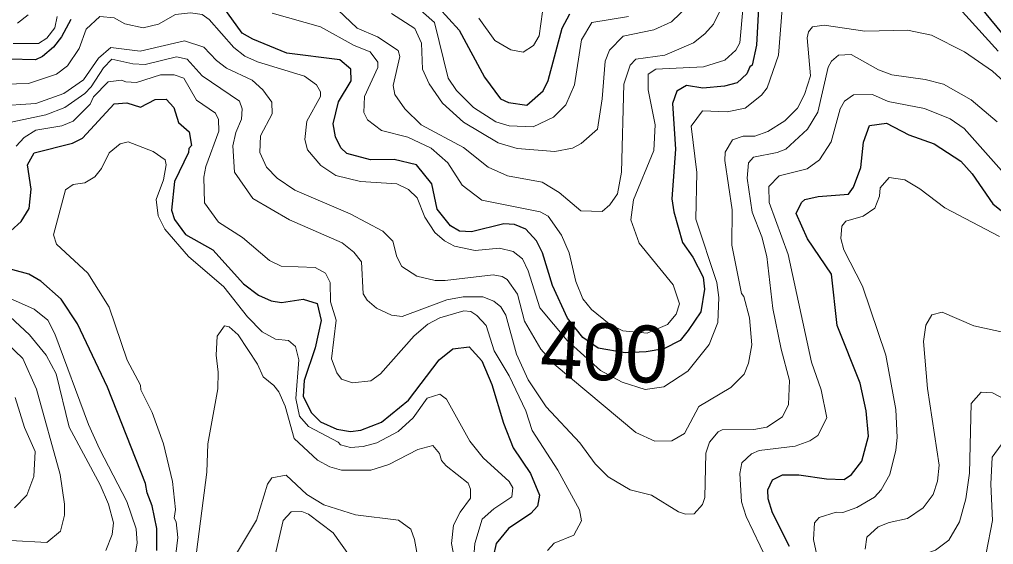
# Model space of a CAD drawing. Extents: x 673.3 to 698.5, y 6984.3 to 7012.3.
# Drawn here: x 682.878 to 684.245, y 6990.82 to 6991.558 of the extents above; entities that cross this region are included whole.
import ezdxf
from ezdxf.enums import TextEntityAlignment as Align

# ---------------------------------------------------------------- set-up
doc = ezdxf.new("R2010")
doc.units = 0
doc.header["$LTSCALE"] = 0.032
doc.layers.add('1', color=7, linetype='Continuous', lineweight=25)
doc.layers.add('2', color=7, linetype='Continuous', lineweight=13)
doc.layers.add('61', color=7, linetype='Continuous')

msp = doc.modelspace()

# ---------------------------------------------------------------- linework, layer by layer
at = {"layer": '1'}
for points in [[(683.917, 6991.6004), (683.9127, 6991.5214), (683.9064, 6991.4935), (683.903, 6991.4911), (683.8991, 6991.4815), (683.8853, 6991.4686), (683.8676, 6991.464), (683.8371, 6991.4611), (683.8145, 6991.4649), (683.8006, 6991.4571), (683.7946, 6991.4397), (683.7988, 6991.3753), (683.7939, 6991.3056), (683.7964, 6991.2876), (683.8086, 6991.2446), (683.8233, 6991.2238), (683.8379, 6991.1957), (683.8394, 6991.179), (683.8346, 6991.1472), (683.8167, 6991.1209), (683.8054, 6991.1069), (683.7824, 6991.0952), (683.7576, 6991.0908), (683.7284, 6991.0894), (683.6901, 6991.096), (683.6689, 6991.1108), (683.647, 6991.1381), (683.6263, 6991.1838), (683.6121, 6991.2301), (683.6037, 6991.2467), (683.5886, 6991.2632), (683.5726, 6991.2696), (683.5576, 6991.2705), (683.5126, 6991.2595), (683.4954, 6991.2603), (683.4829, 6991.268), (683.4641, 6991.291), (683.4565, 6991.327), (683.4354, 6991.3536), (683.4036, 6991.3609), (683.3704, 6991.3606), (683.3372, 6991.3696), (683.3289, 6991.3773), (683.3213, 6991.393), (683.3183, 6991.4109), (683.3258, 6991.4419), (683.3434, 6991.4713), (683.343, 6991.4877), (683.3277, 6991.501), (683.2529, 6991.5101), (683.2052, 6991.5299), (683.1906, 6991.5383), (683.1455, 6991.6011)], [(684.257, 6991.5387), (684.1974, 6991.6113)], [(683.4662, 6991.5746), (683.4951, 6991.5424), (683.5307, 6991.4764), (683.5531, 6991.4462), (683.5644, 6991.441), (683.5901, 6991.4374), (683.6131, 6991.4574), (683.6202, 6991.4719), (683.6399, 6991.5455), (683.6507, 6991.5655)], [(682.9497, 6991.5577), (682.9365, 6991.5331), (682.9255, 6991.5187), (682.91, 6991.5058), (682.9004, 6991.5011), (682.8631, 6991.5019)], [(682.8803, 6991.2741), (682.8913, 6991.292), (682.8939, 6991.3194), (682.8891, 6991.3534), (682.8985, 6991.3702), (682.9521, 6991.3841), (682.9662, 6991.391), (683.0108, 6991.4391), (683.0286, 6991.4407), (683.0476, 6991.4343), (683.0684, 6991.4453), (683.0837, 6991.4455), (683.0943, 6991.4339), (683.1011, 6991.4128), (683.1161, 6991.4), (683.1194, 6991.3806), (683.1156, 6991.3764), (683.1151, 6991.371), (683.0954, 6991.3299), (683.0911, 6991.2896), (683.0953, 6991.2768), (683.1109, 6991.2558), (683.1492, 6991.2342), (683.1923, 6991.1865), (683.2134, 6991.1703), (683.2312, 6991.1625), (683.2454, 6991.16), (683.2762, 6991.1646), (683.2955, 6991.1587), (683.3011, 6991.1346), (683.2931, 6991.0966), (683.2775, 6991.0504), (683.2759, 6991.0285), (683.2872, 6991.0054), (683.3006, 6990.9927), (683.3235, 6990.9822), (683.3424, 6990.9791), (683.357, 6990.9806), (683.3861, 6990.9922), (683.424, 6991.0228), (683.4672, 6991.0798), (683.4864, 6991.0951), (683.5093, 6991.0979), (683.5267, 6991.0783), (683.5411, 6991.0448), (683.5573, 6990.9905), (683.5709, 6990.956), (683.5953, 6990.9201), (683.608, 6990.8897), (683.6049, 6990.8739), (683.5956, 6990.8639), (683.5643, 6990.8425), (683.547, 6990.8216), (683.543, 6990.8028)], [(683.9589, 6990.8174), (683.9349, 6990.8647), (683.9291, 6990.8845), (683.9285, 6990.8972), (683.935, 6990.9112), (683.9489, 6990.9179), (683.9722, 6990.9179), (684.0107, 6990.9122), (684.0358, 6990.9116), (684.0459, 6990.9185), (684.0607, 6990.9371), (684.0699, 6990.9725), (684.0667, 6991.008), (684.0583, 6991.0466), (684.0259, 6991.128), (684.0178, 6991.2), (683.9843, 6991.2497), (683.9683, 6991.2852), (683.9756, 6991.3008), (683.9804, 6991.3047), (683.999, 6991.3088), (684.0416, 6991.3124), (684.0487, 6991.3219), (684.0593, 6991.3499), (684.0628, 6991.3854), (684.0714, 6991.4086), (684.0949, 6991.4119), (684.1264, 6991.3958)], [(684.1264, 6991.3958), (684.1622, 6991.3828), (684.1994, 6991.3585), (684.2154, 6991.3408), (684.2445, 6991.2988), (684.2832, 6991.2673)], [(682.836, 6991.2346), (682.8803, 6991.2741)], [(683.0706, 6990.8117), (683.0706, 6990.8425), (683.0642, 6990.8745), (683.0568, 6990.8929), (683.0546, 6990.9061), (683.0013, 6991.0412), (682.9593, 6991.1302), (682.9362, 6991.1649), (682.9076, 6991.1901), (682.8909, 6991.1997), (682.8405, 6991.2135)]]:
    msp.add_lwpolyline(points, dxfattribs=at)
at = {"layer": '2'}
for points in [[(683.2982, 6991.5968), (683.3519, 6991.5455), (683.3804, 6991.5334), (683.4092, 6991.5141), (683.4117, 6991.5056), (683.4022, 6991.4647), (683.4046, 6991.4521), (683.419, 6991.4321), (683.4415, 6991.4095), (683.5014, 6991.3778), (683.5359, 6991.3502), (683.5631, 6991.338), (683.6117, 6991.329), (683.6356, 6991.3147), (683.6658, 6991.289), (683.6959, 6991.2878), (683.7066, 6991.2973), (683.7173, 6991.3126), (683.7229, 6991.3432), (683.7263, 6991.4666), (683.7352, 6991.4935), (683.7432, 6991.502), (683.7837, 6991.5075), (683.8239, 6991.525), (683.8399, 6991.5373), (683.852, 6991.551), (683.865, 6991.5769)], [(683.8173, 6991.5773), (683.7933, 6991.5542), (683.7682, 6991.543), (683.7252, 6991.5342), (683.7063, 6991.5146), (683.7002, 6991.4993), (683.6961, 6991.4462), (683.6895, 6991.4035), (683.6665, 6991.3836), (683.6542, 6991.3769), (683.6293, 6991.3723), (683.5765, 6991.3765), (683.5499, 6991.3843), (683.5012, 6991.4134), (683.4719, 6991.4402), (683.4529, 6991.4671), (683.4437, 6991.4879), (683.442, 6991.5246), (683.4328, 6991.5451), (683.3999, 6991.566)], [(683.426, 6991.5839), (683.4605, 6991.5533), (683.4797, 6991.4752), (683.4912, 6991.4577), (683.5151, 6991.4338), (683.5465, 6991.4137), (683.5652, 6991.4082), (683.5991, 6991.4067), (683.6277, 6991.4202), (683.6448, 6991.4376), (683.6572, 6991.466), (683.6667, 6991.5292), (683.6813, 6991.5535), (683.7329, 6991.562)], [(683.894, 6991.5768), (683.8891, 6991.5247), (683.8835, 6991.5145), (683.8681, 6991.5006), (683.8383, 6991.4913), (683.7713, 6991.488), (683.7603, 6991.4806), (683.7603, 6991.459), (683.7702, 6991.4096), (683.7686, 6991.3738), (683.7398, 6991.3042), (683.7361, 6991.276), (683.7477, 6991.2433), (683.7958, 6991.1848), (683.8045, 6991.1584), (683.7996, 6991.1438), (683.7876, 6991.1293), (683.759, 6991.1171), (683.725, 6991.1202), (683.7058, 6991.1303), (683.6811, 6991.1505), (683.6689, 6991.1653)], [(684.1929, 6991.5783), (684.2517, 6991.513)], [(682.8567, 6991.4669), (682.8902, 6991.4677), (682.9297, 6991.481), (682.945, 6991.4926), (682.9614, 6991.5171), (682.9714, 6991.5442), (682.9906, 6991.5619), (683.0105, 6991.5598), (683.0257, 6991.5513), (683.0512, 6991.5458), (683.073, 6991.5511), (683.0968, 6991.5645), (683.1179, 6991.5671), (683.1342, 6991.5645), (683.1441, 6991.5578)], [(682.9305, 6991.5618), (682.9273, 6991.5461), (682.9159, 6991.5312), (682.9045, 6991.5239), (682.8688, 6991.5239)], [(682.8751, 6991.5525), (682.8899, 6991.5644)], [(683.1441, 6991.5578), (683.1788, 6991.5184), (683.1942, 6991.5062), (683.2117, 6991.4982), (683.2778, 6991.4781), (683.2946, 6991.466), (683.3002, 6991.4562), (683.3003, 6991.4493), (683.2811, 6991.4149), (683.2784, 6991.3891), (683.282, 6991.3747), (683.3009, 6991.3524), (683.3217, 6991.3385), (683.3567, 6991.3301), (683.4075, 6991.3267), (683.4241, 6991.3186), (683.4362, 6991.3072), (683.447, 6991.2799), (683.4611, 6991.2586), (683.4746, 6991.2465), (683.4884, 6991.2391), (683.5176, 6991.2331), (683.5517, 6991.2363), (683.5711, 6991.2317), (683.5838, 6991.2214), (683.5922, 6991.2047), (683.6084, 6991.1525), (683.6467, 6991.1065), (683.6934, 6991.0646), (683.7241, 6991.048), (683.7564, 6991.0377), (683.7827, 6991.0415), (683.8164, 6991.0635), (683.8459, 6991.1013), (683.8581, 6991.1322), (683.8597, 6991.167), (683.8567, 6991.1884), (683.8273, 6991.2771), (683.8288, 6991.3426), (683.8209, 6991.4079), (683.8369, 6991.4291), (683.8716, 6991.4278), (683.8968, 6991.433), (683.9197, 6991.4511), (683.9274, 6991.4614), (683.9437, 6991.5074), (683.9484, 6991.5728)], [(683.6689, 6991.1653), (683.6591, 6991.1895), (683.6495, 6991.2301), (683.6389, 6991.2546), (683.6199, 6991.2816), (683.6086, 6991.2876), (683.527, 6991.3038), (683.4995, 6991.3247), (683.4792, 6991.3563), (683.4556, 6991.3771), (683.4231, 6991.3925), (683.386, 6991.4019), (683.3665, 6991.4168), (683.3614, 6991.4269), (683.3621, 6991.4495), (683.381, 6991.49), (683.3808, 6991.4979), (683.3702, 6991.5123), (683.3478, 6991.5212), (683.3006, 6991.5473), (683.2327, 6991.5666)], [(683.6123, 6991.5686), (683.6073, 6991.5345), (683.5995, 6991.5209), (683.585, 6991.5117), (683.5677, 6991.5152), (683.545, 6991.5283), (683.5225, 6991.5596)], [(683.9014, 6991.0748), (683.9062, 6991.1006), (683.9029, 6991.1386), (683.8949, 6991.1685), (683.8916, 6991.1729), (683.8778, 6991.2406), (683.8785, 6991.2904), (683.868, 6991.3595), (683.8684, 6991.3711), (683.8789, 6991.3886), (683.8938, 6991.3936), (683.9101, 6991.3937), (683.9285, 6991.4005), (683.9526, 6991.4152), (683.9703, 6991.4332), (683.9799, 6991.4522), (683.9883, 6991.4784), (683.9836, 6991.5317), (683.9856, 6991.5401), (683.9912, 6991.5475), (684.0075, 6991.5498), (684.0649, 6991.541), (684.1248, 6991.5425), (684.1582, 6991.5354), (684.2046, 6991.5123), (684.2438, 6991.4851), (684.2702, 6991.4612)], [(682.8446, 6991.436), (682.9008, 6991.4396), (682.9401, 6991.4536), (682.9676, 6991.473), (682.9888, 6991.5031), (683.0059, 6991.5181), (683.0472, 6991.5133), (683.1095, 6991.5277), (683.1365, 6991.5188), (683.1543, 6991.5), (683.1686, 6991.4892), (683.2042, 6991.4725), (683.2192, 6991.459), (683.232, 6991.4417), (683.2326, 6991.4251), (683.216, 6991.3944), (683.2152, 6991.3709), (683.2247, 6991.3502), (683.2395, 6991.3346), (683.2645, 6991.3177), (683.3422, 6991.2846), (683.3881, 6991.2601), (683.4019, 6991.2463), (683.4075, 6991.2241), (683.4147, 6991.2107), (683.4355, 6991.1971), (683.4616, 6991.1912), (683.4752, 6991.1908), (683.5426, 6991.1989), (683.5554, 6991.1966), (683.5623, 6991.1924), (683.5772, 6991.172), (683.5869, 6991.134), (683.6099, 6991.0944), (683.6287, 6991.0734), (683.7431, 6990.9775), (683.7697, 6990.9651), (683.7935, 6990.9659), (683.8114, 6990.9763), (683.8315, 6991.0142), (683.8767, 6991.0407), (683.8954, 6991.0594), (683.9014, 6991.0748)], [(682.866, 6991.4132), (682.9146, 6991.4237), (682.9416, 6991.4342), (682.9693, 6991.4535), (682.9784, 6991.4632), (682.9956, 6991.4898), (683.0075, 6991.5017), (683.0367, 6991.4953), (683.0541, 6991.4946), (683.0983, 6991.5051), (683.1133, 6991.502), (683.1341, 6991.4784), (683.1866, 6991.4427), (683.1903, 6991.4323), (683.1896, 6991.4177), (683.1814, 6991.3989), (683.1774, 6991.38), (683.1796, 6991.3432), (683.2052, 6991.3064), (683.2569, 6991.276), (683.3308, 6991.2439), (683.3471, 6991.231), (683.3581, 6991.2174), (683.3605, 6991.1723), (683.3658, 6991.1634), (683.3791, 6991.1521), (683.4003, 6991.1422), (683.4151, 6991.1403), (683.4779, 6991.1638), (683.5009, 6991.168), (683.5283, 6991.1679), (683.5436, 6991.1622), (683.5536, 6991.1541), (683.5608, 6991.1422), (683.5757, 6991.0875), (683.592, 6991.0513), (683.6174, 6991.0135), (683.6647, 6990.9632), (683.686, 6990.9337), (683.7042, 6990.9154), (683.7352, 6990.8972), (683.7653, 6990.8894), (683.8031, 6990.8661), (683.8128, 6990.8627), (683.8252, 6990.8632), (683.8369, 6990.8763), (683.8402, 6990.8863), (683.8416, 6990.9487), (683.8467, 6990.9641), (683.8587, 6990.9786), (683.8642, 6990.9814), (683.9088, 6990.9815), (683.9271, 6990.9852), (683.9489, 6990.9997), (683.9575, 6991.0166), (683.9591, 6991.0507), (683.947, 6991.0944), (683.9355, 6991.1519)], [(683.9355, 6991.1519), (683.9273, 6991.2249), (683.9201, 6991.2524), (683.9063, 6991.2871), (683.8997, 6991.3347), (683.9014, 6991.3565), (683.9082, 6991.3642), (683.9417, 6991.3707), (683.9539, 6991.3756), (683.9841, 6991.4036), (683.9985, 6991.4275), (684.013, 6991.4907), (684.018, 6991.4989), (684.0275, 6991.5074), (684.0454, 6991.5083), (684.084, 6991.487), (684.1027, 6991.48), (684.1495, 6991.4732), (684.1753, 6991.4667), (684.2138, 6991.445), (684.2506, 6991.4138)], [(682.8729, 6991.3798), (682.8845, 6991.3919), (682.9007, 6991.4021), (682.9374, 6991.4082), (682.9531, 6991.4146), (682.9768, 6991.4389), (682.9818, 6991.449), (683.002, 6991.4701), (683.021, 6991.4726), (683.027, 6991.47), (683.0421, 6991.4693), (683.0755, 6991.4798), (683.0951, 6991.4798), (683.1085, 6991.4751), (683.1263, 6991.4445), (683.1529, 6991.4259), (683.157, 6991.4173), (683.1577, 6991.4008), (683.1396, 6991.3511), (683.1367, 6991.3363), (683.1375, 6991.3), (683.1571, 6991.2728), (683.191, 6991.2512), (683.2289, 6991.2191), (683.2452, 6991.2112), (683.2928, 6991.2093), (683.3075, 6991.2015), (683.3141, 6991.188), (683.3142, 6991.1612), (683.3223, 6991.1354), (683.3158, 6991.0809), (683.3235, 6991.0613), (683.3298, 6991.0524), (683.3453, 6991.0475), (683.371, 6991.0499), (683.3845, 6991.06), (683.432, 6991.1132), (683.4512, 6991.1298), (683.4681, 6991.1386), (683.5017, 6991.1482), (683.5114, 6991.1476), (683.52, 6991.142), (683.5331, 6991.1279), (683.5444, 6991.092), (683.5651, 6991.057), (683.5889, 6991.0078), (683.5977, 6990.9804), (683.6337, 6990.9248), (683.6639, 6990.8689), (683.6667, 6990.8536), (683.656, 6990.8335), (683.6287, 6990.8219), (683.6192, 6990.8117)], [(683.9275, 6990.7976), (683.8983, 6990.8596), (683.8915, 6990.8799), (683.8891, 6990.92), (683.8922, 6990.9351), (683.9054, 6990.9474), (683.9161, 6990.9521), (683.9671, 6990.9584), (683.9874, 6990.9658), (683.9987, 6990.9731), (684.0113, 6990.9982), (684.0032, 6991.0374), (683.9897, 6991.0765), (683.9569, 6991.2276), (683.9305, 6991.3005), (683.9299, 6991.3232), (683.9446, 6991.3382), (683.9838, 6991.3477), (684.0009, 6991.3605), (684.0175, 6991.3857), (684.0301, 6991.4321), (684.0361, 6991.4427), (684.0487, 6991.452), (684.0756, 6991.4521)], [(684.0756, 6991.4521), (684.0974, 6991.4426), (684.1484, 6991.4328), (684.1845, 6991.4181), (684.2041, 6991.4043), (684.2751, 6991.3244)], [(683.5162, 6990.8094), (683.5173, 6990.8214), (683.5275, 6990.8558), (683.5436, 6990.8704), (683.5691, 6990.8871), (683.5706, 6990.9), (683.5655, 6990.9086), (683.5288, 6990.942), (683.51, 6990.9655), (683.4772, 6991.0244), (683.468, 6991.0312), (683.45, 6991.0258), (683.4307, 6990.9979), (683.4094, 6990.9787), (683.3796, 6990.9629), (683.3604, 6990.9578), (683.3427, 6990.9563), (683.3283, 6990.9603), (683.3251, 6990.9641), (683.2836, 6990.9859), (683.2711, 6991.0005), (683.2657, 6991.0253), (683.2698, 6991.0797), (683.2652, 6991.0985), (683.2553, 6991.1068), (683.2374, 6991.1088), (683.2184, 6991.1187), (683.1981, 6991.1398), (683.1647, 6991.1822), (683.115, 6991.2245), (683.0816, 6991.2631), (683.0726, 6991.282), (683.0698, 6991.3047), (683.0797, 6991.3322), (683.0837, 6991.3534), (683.0821, 6991.3607), (683.0656, 6991.3724), (683.0305, 6991.386), (683.0191, 6991.3831), (683.0035, 6991.3704), (682.9931, 6991.3485), (682.9837, 6991.3367), (682.9695, 6991.3283), (682.9533, 6991.3258), (682.9425, 6991.3182), (682.9257, 6991.255), (682.9299, 6991.2421), (682.9739, 6991.2011), (683.0037, 6991.1536), (683.0287, 6991.0792), (683.0478, 6991.0438), (683.048, 6991.0376), (683.064, 6991.0054), (683.0797, 6990.9617), (683.0927, 6990.9085), (683.0966, 6990.8694), (683.0951, 6990.857), (683.0976, 6990.8521), (683.0999, 6990.8298), (683.0951, 6990.7868)], [(684.2537, 6991.2528), (684.1772, 6991.2931), (684.1421, 6991.3196), (684.1207, 6991.3323), (684.0987, 6991.3357), (684.0862, 6991.3214), (684.0852, 6991.3096), (684.0786, 6991.2924), (684.0625, 6991.2812), (684.0382, 6991.2745), (684.0325, 6991.2672), (684.0308, 6991.2499), (684.0351, 6991.2341), (684.0615, 6991.1832), (684.0944, 6991.0863), (684.1081, 6991.0099), (684.1099, 6990.9707), (684.1082, 6990.9529), (684.1, 6990.9187), (684.0877, 6990.8969), (684.0783, 6990.8866), (684.0537, 6990.872), (684.0337, 6990.8651), (684.0245, 6990.8657), (684.0004, 6990.8581)], [(683.0399, 6990.8037), (683.0429, 6990.822), (683.0414, 6990.842), (683.0286, 6990.8808), (682.99, 6990.9544), (682.9747, 6990.9886), (682.9272, 6991.1161), (682.9177, 6991.1351), (682.8983, 6991.1507), (682.8462, 6991.1735)], [(682.9989, 6990.8117), (683.008, 6990.8343), (683.0095, 6990.8505), (683.0026, 6990.877), (682.9909, 6990.9039), (682.9476, 6990.9851), (682.929, 6991.0601), (682.9153, 6991.0863), (682.8918, 6991.1147), (682.8646, 6991.1402)], [(684.0651, 6990.8136), (684.0673, 6990.8303), (684.0836, 6990.845), (684.0987, 6990.8512), (684.1245, 6990.8569), (684.1464, 6990.8717), (684.1608, 6990.8906), (684.1669, 6990.9093), (684.1692, 6990.9318), (684.1529, 6991.0393), (684.1473, 6991.1051), (684.1502, 6991.1285), (684.1587, 6991.1428), (684.1735, 6991.1466), (684.2179, 6991.1271), (684.3036, 6991.1084)], [(683.1209, 6990.7696), (683.1407, 6990.9218), (683.1424, 6990.9617), (683.1563, 6991.039), (683.1569, 6991.0624), (683.1538, 6991.0863), (683.1554, 6991.1126), (683.1654, 6991.1271), (683.1722, 6991.126), (683.1847, 6991.1148), (683.2117, 6991.0733), (683.2199, 6991.0555), (683.235, 6991.0435), (683.2421, 6991.0344), (683.2507, 6991.0146), (683.2633, 6990.9691), (683.296, 6990.9385), (683.3133, 6990.9294), (683.3299, 6990.9244), (683.3709, 6990.9245), (683.3962, 6990.9324), (683.4371, 6990.9538), (683.4581, 6990.9594), (683.4677, 6990.9478), (683.4702, 6990.9383), (683.4767, 6990.9305), (683.5076, 6990.9062), (683.5112, 6990.8978), (683.5111, 6990.8852), (683.4966, 6990.8658), (683.487, 6990.8474), (683.4843, 6990.8217), (683.4909, 6990.7869)], [(682.8649, 6990.8259), (682.9159, 6990.8228), (682.9355, 6990.8387), (682.9411, 6990.8615), (682.9411, 6990.8769), (682.9347, 6990.9184), (682.9016, 6991.0383), (682.8826, 6991.0814), (682.8489, 6991.1135)], [(682.8706, 6990.8717), (682.8879, 6990.8897), (682.898, 6990.9155), (682.8996, 6990.951), (682.8847, 6990.9846), (682.8718, 6991.0265)], [(684.312, 6990.9976), (684.244, 6991.0333), (684.2281, 6991.0343), (684.2142, 6991.0183), (684.2116, 6990.9202), (684.2067, 6990.8843), (684.1976, 6990.8518), (684.1827, 6990.8263), (684.1638, 6990.8122), (684.1438, 6990.8053), (684.1367, 6990.7987), (684.135, 6990.7884), (684.1395, 6990.7729), (684.1545, 6990.7469), (684.2055, 6990.688), (684.2166, 6990.6701), (684.2278, 6990.6386), (684.2278, 6990.625), (684.2225, 6990.6139)], [(684.2734, 6990.6601), (684.2168, 6990.7391), (684.2145, 6990.7509), (684.2149, 6990.7736), (684.2351, 6990.8078), (684.2442, 6990.854), (684.2418, 6990.9048), (684.2434, 6990.9428), (684.2562, 6990.9603)], [(683.4376, 6990.7985), (683.4323, 6990.8272), (683.4271, 6990.8415), (683.4097, 6990.8545), (683.3493, 6990.8617), (683.305, 6990.8757), (683.2811, 6990.8906), (683.2521, 6990.9178), (683.2321, 6990.9137), (683.2261, 6990.9051), (683.2103, 6990.8543), (683.1644, 6990.7773)], [(683.2369, 6990.805), (683.2479, 6990.8537), (683.2593, 6990.8659), (683.274, 6990.8666), (683.2835, 6990.8626), (683.3181, 6990.8365), (683.3411, 6990.8045)], [(684.0004, 6990.8581), (683.9942, 6990.8504), (683.9926, 6990.8273), (683.9973, 6990.8053)]]:
    msp.add_lwpolyline(points, dxfattribs=at)

# ---------------------------------------------------------------- texts
at = {"layer": '61'}
msp.add_text('400', height=0.08, rotation=357.064, dxfattribs=at).set_placement((683.6967, 6991.0509), align=Align.CENTER)

doc.saveas('drawing.dxf')
